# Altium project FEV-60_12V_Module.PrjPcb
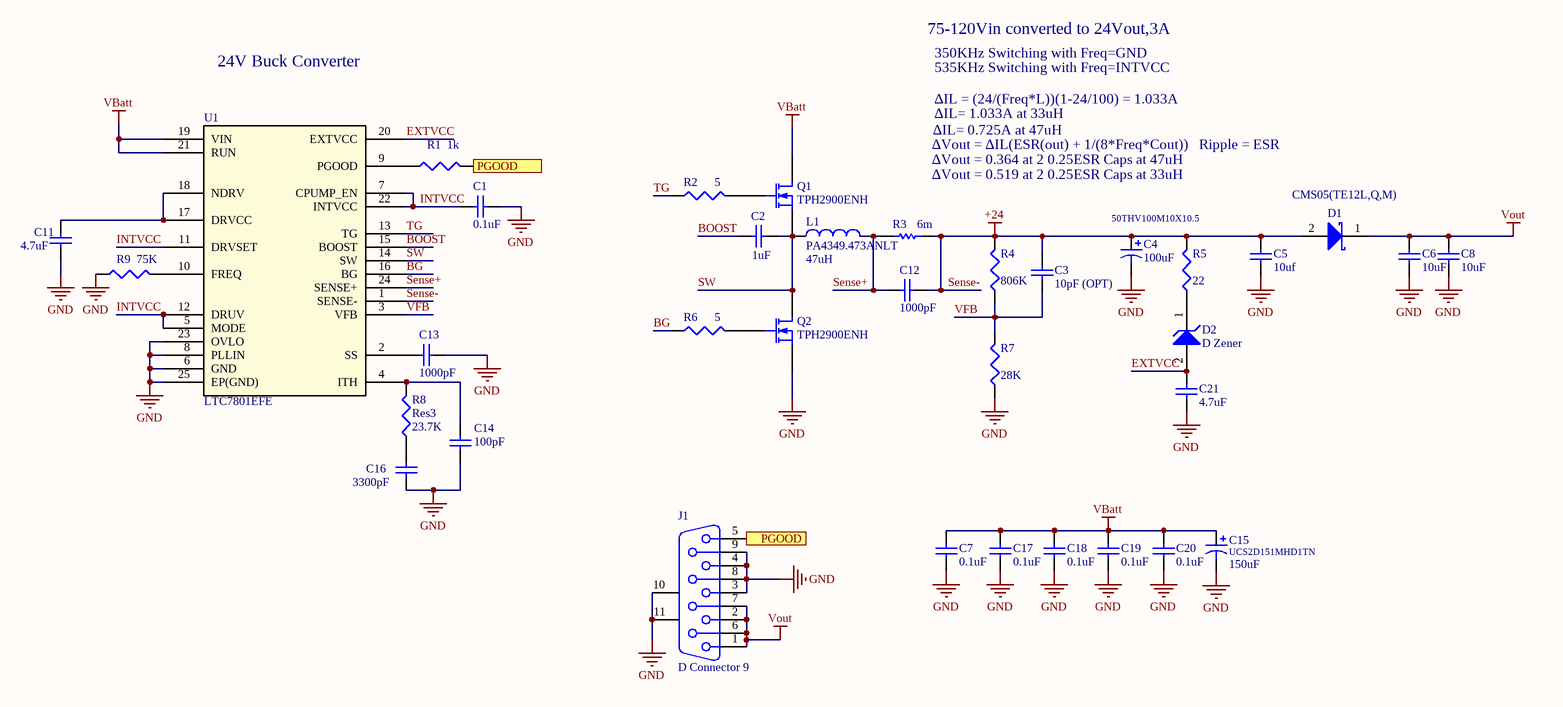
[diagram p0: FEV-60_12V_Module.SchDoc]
Rev: A0
1 sheet, 35 parts. Net scope: flat (ports and power ports of the same name join across sheets).
Board file: FEV-60_12V_Module.PcbDoc

## Sheet FEV-60_12V_Module.SchDoc
size B

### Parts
C1  value 0.1uF  [1608[0603]]  (hidden comment: Cap Semi)
C2  value 1uF  [1608[0603]]  (hidden comment: Cap Semi)
C3  value 10pF (OPT)  [1608[0603]]  (hidden comment: Cap Semi)
C4  50THV100M10X10.5  value 100uF  [CAP_J-V_10X10P5]
C5  value 10uf  [C1206]  (hidden comment: Cap Semi)
C6  value 10uF  [C1206]  (hidden comment: Cap Semi)
C7  value 0.1uF  [C1206]  (hidden comment: Cap Semi)
C8  value 10uF  [C1206]  (hidden comment: Cap Semi)
C11  value 4.7uF  [1608[0603]]  (hidden comment: Cap Semi)
C12  value 1000pF  [1608[0603]]  (hidden comment: Cap Semi)
C13  value 1000pF  [1608[0603]]  (hidden comment: Cap Semi)
C14  value 100pF  [1608[0603]]  (hidden comment: Cap Semi)
C15  UCS2D151MHD1TN  value 150uF  [UCS2D151MHD1TN]
C16  value 3300pF  [1608[0603]]  (hidden comment: Cap Semi)
C17  value 0.1uF  [C1206]  (hidden comment: Cap Semi)
C18  value 0.1uF  [C1206]  (hidden comment: Cap Semi)
C19  value 0.1uF  [C1206]  (hidden comment: Cap Semi)
C20  value 0.1uF  [C1206]  (hidden comment: Cap Semi)
C21  value 4.7uF  [1608[0603]]  (hidden comment: Cap Semi)
D1  CMS05(TE12L,Q,M)  [CMS05(TE12L,Q,M)]
D2  D Zener  [SMA]
J1  D Connector 9  [DSUB1.385-2H9]
L1  PA4349.473ANLT  value 47uH  [PA4349.473ANLT]
Q1  TPH2900ENH  [TPH2900ENH]
Q2  TPH2900ENH  [TPH2900ENH]
R1  value 1k  [J1-0603]  (hidden comment: Res3)
R2  value 5  [J1-0603]  (hidden comment: Res3)
R3  6m  [RESC2512(6432)_L]
R4  value 806K  [J1-0603]  (hidden comment: Res3)
R5  value 22  [J1-0603]  (hidden comment: Res3)
R6  value 5  [J1-0603]  (hidden comment: Res3)
R7  value 28K  [J1-0603]  (hidden comment: Res3)
R8  Res3  value 23.7K  [J1-0603]
R9  value 75K  [J1-0603]  (hidden comment: Res3)
U1  LTC7801EFE  [LTC7801]

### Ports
PGOOD (out)

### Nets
GND: C1.1 C4.2 C5.1 C6.1 C7.1 C8.1 C11.1 C13.1 C14.1 C15.2 C16.1 C17.1 C18.1 C19.1 C20.1 C21.1 J1.3 J1.4 J1.8 J1.9 J1.10(MH1) J1.11(MH2) Q2.3(S) R7.1 R9.1 U1.6(GND) U1.8(PLLIN) U1.23(OVLO) U1.25(EP(GND))
Sense-: C3.2 C4.1 C5.2 C12.1 D1.2(A) R3.2 R4.2 R5.2 U1.1(SENSE-)  [also labelled +24]
VBatt: C7.2 C15.1 C17.2 C18.2 C19.2 C20.2 Q1.1(D) U1.19(VIN) U1.21(RUN)
Vout: C6.2 C8.2 D1.1(K) J1.1 J1.2 J1.6 J1.7
BG: R6.1 U1.16(BG)
BOOST: C2.2 U1.15(BOOST)
EXTVCC: C21.2 D2.2(A) U1.20(EXTVCC)
INTVCC: C1.2 U1.5(MODE) U1.7(CPUMP_EN) U1.11(DRVSET) U1.12(DRUV) U1.22(INTVCC)
Sense+: C12.2 L1.2 R3.1 U1.24(SENSE+)
SW: C2.1 L1.1 Q1.3(S) Q2.1(D) U1.14(SW)
TG: R2.1 U1.13(TG)
VFB: C3.1 R4.1 R7.2 U1.3(VFB)
NetC11_2: C11.2 U1.17(DRVCC) U1.18(NDRV)
NetC13_2: C13.2 U1.2(SS)
NetC14_2: C14.2 R8.2 U1.4(ITH)
NetC16_2: C16.2 R8.1
NetD2_1: D2.1(K) R5.1
NetJ1_5: J1.5 R1.2 ; port PGOOD
NetQ1_2: Q1.2(G) R2.2
NetQ2_2: Q2.2(G) R6.2
NetR1_1: R1.1 U1.9(PGOOD)
NetR9_2: R9.2 U1.10(FREQ)

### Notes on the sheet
- 24V Buck Converter
- 75-120Vin converted to 24Vout,3A
- 350KHz Switching with Freq=GND
- 535KHz Switching with Freq=INTVCC
- ∆Vout = ∆IL(ESR(out) + 1/(8*Freq*Cout))   Ripple = ESR
- ∆IL= 0.725A at 47uH
- ∆IL = (24/(Freq*L))(1-24/100) = 1.033A
- ∆IL= 1.033A at 33uH
- ∆Vout = 0.364 at 2 0.25ESR Caps at 47uH
- ∆Vout = 0.519 at 2 0.25ESR Caps at 33uH

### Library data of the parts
C1-C3 C5-C8 C11-C14 C16-C21 = Cap Semi: Capacitor (Semiconductor SIM Model)
C4 C15 = Cap Pol3: Polarized Capacitor (Surface Mount)
D1 = Diode 10TQ035: Schottky Rectifier; Manufacturer: Toshiba; Note: Terminal 2 is the TAB and is electrically connected to the cathode
D2 = D Zener: Zener Diode
J1 = D Connector 9: Receptacle Assembly, 9 Position, Right Angle; PackageDocument: O; Positions: 9
L1 = Inductor: Code_IEC: 1005
Q1 Q2 = TPH2900ENH: N-Channel 200V 33A (Ta) 78W (Tc) Surface Mount 8-SOP Advance (5x5); Manufacturer: Toshiba; Part Number: TPH2900ENHL1QCT-ND
R1 R2 R4-R9 = Res3: Resistor
R3 = CMP-1018-00006-1: 2512; Manufacturer: Rohm Semiconductor; Part Number: PMR100HZPFU6L00; Tolerance: 5 %; Case-Metric: 6432; Value: 1.50 Ohm; Power: 1 W
U1 = LTC7801EFE: Buck Regulator Positive Output Step-Down DC-DC Controller IC 24-TSSOP; Manufacturer: Analog Devices; Part Number: LTC7801EFE#PBF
